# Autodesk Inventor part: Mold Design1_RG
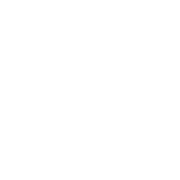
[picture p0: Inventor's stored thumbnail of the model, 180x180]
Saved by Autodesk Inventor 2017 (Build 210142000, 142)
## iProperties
Created: 2016-07
Part Number: Mold Design1_RG
Material: Generic
Document SubType Name: Modeling
Designer: Sandeep
Density: 1 g/cm^3
Appearance: Default
Author: Sandeep
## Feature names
1. Extrusion4
2. Extrusion5
3. Extrusion6
4. Sweep1
5. Revolution1
6. Extrusion1
7. Sweep2
8. Revolution2
9. Extrusion2
10. Sweep3
11. Revolution3
12. Extrusion3
13. Revolution4
14. Revolution5
15. Revolution6
## Parameters: d0 = 0, d1 = 4 mm, d2 = 0, d3 = 0, d4 = 4 mm, d5 = 4 mm, d6 = 180 deg, d7 = 4 mm, d8 = 4 mm, d9 = 0, d10 = 4 mm, d11 = 0, d12 = 0, d13 = -4 mm, d14 = 4 mm, d15 = 180 deg, d16 = 4 mm, d17 = 4 mm, d18 = 0, d19 = 4 mm, d20 = 0, d21 = 0, d22 = 4 mm, d23 = 4 mm, d24 = 180 deg, d25 = 4 mm, d26 = 4 mm, d27 = 0, d28 = 5 mm, d30 = 80 deg, d31 = 80 deg, d32 = 0, d33 = 5 mm, d35 = 80 deg, d36 = 80 deg, d37 = 0, d38 = 5 mm, d40 = 80 deg, d41 = 80 deg, d42 = 0, d43 = 8 mm, d44 = 5 deg, d45 = 8 mm, d46 = 5 deg, d47 = 8 mm, d48 = 5 deg
